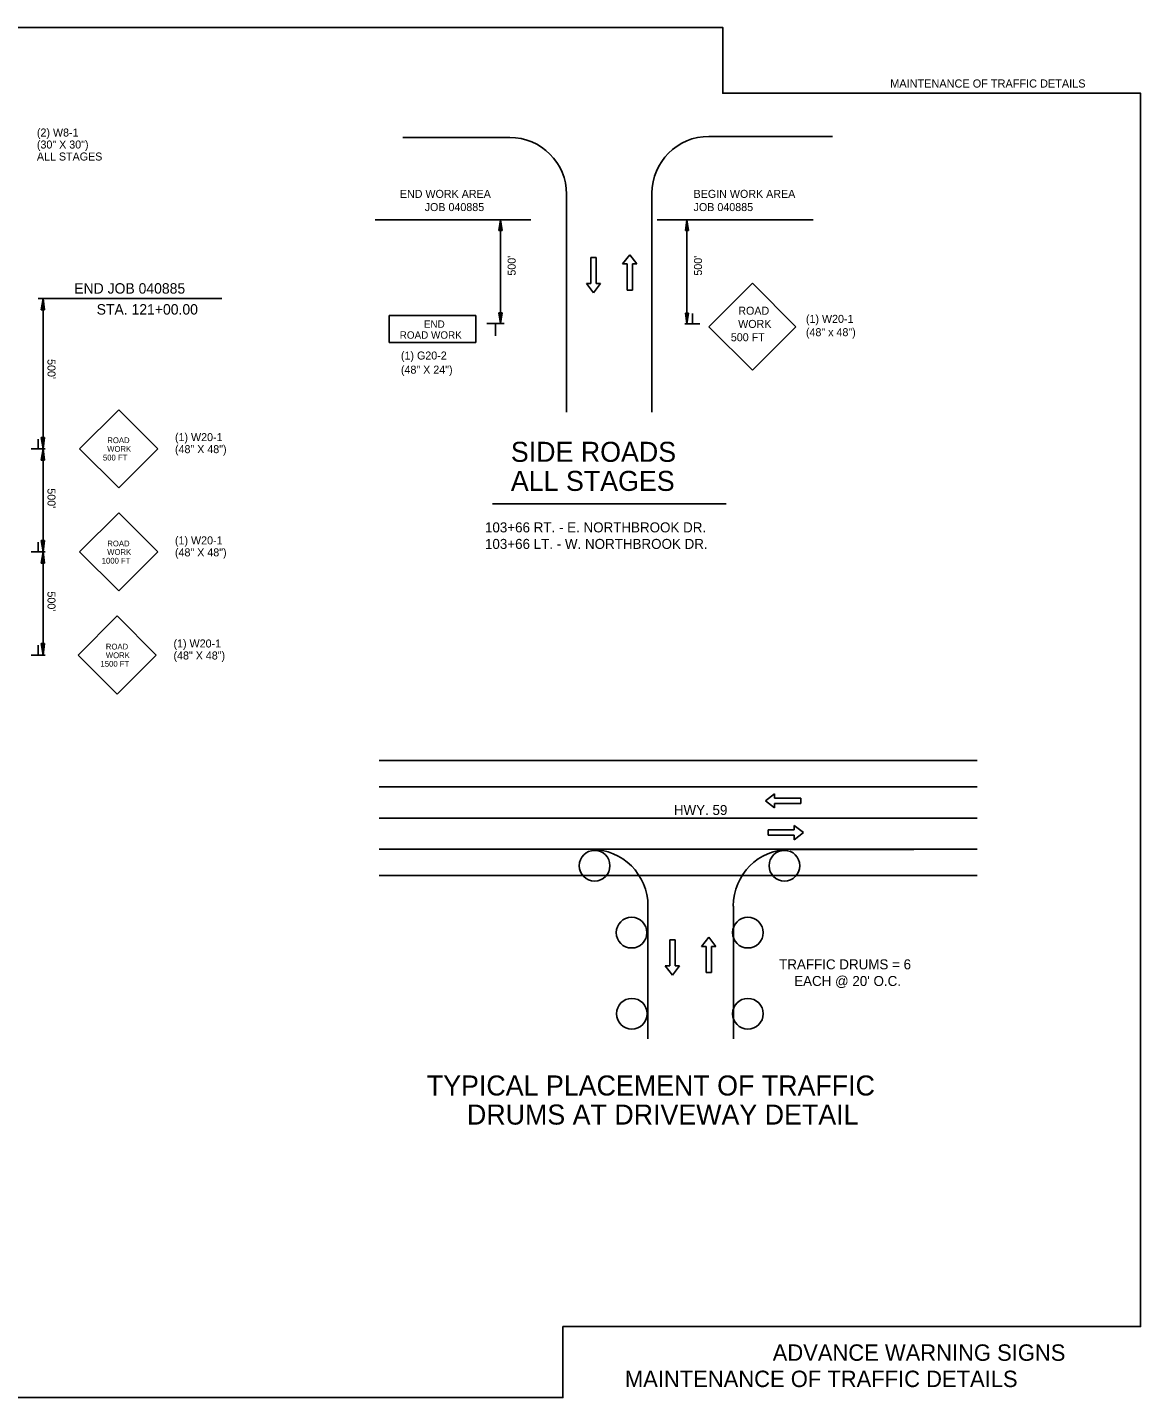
# Model space of a CAD drawing. Extents: x 612778 to 616168, y 428753 to 429781.
# Drawn here: x 613525 to 614359, y 428753 to 429781 of the extents above; entities that cross this region are included whole.
import ezdxf

# ---------------------------------------------------------------- set-up
doc = ezdxf.new("R2010")
doc.units = 0
for name, color, linetype in [('Level 8', 7, 'Continuous'), ('Plan Notes', 7, 'Continuous'), ('R_Draft', 7, 'Continuous'), ('R_No Plot', 7, 'Continuous'), ('STAGE 1 BARRELS', 7, 'Continuous')]:
    doc.layers.add(name, color=color, linetype=linetype)

msp = doc.modelspace()

# ---------------------------------------------------------------- linework, layer by layer
at = {"layer": 'Level 8'}
for p, q in [((613593.3, 429493.9), (613564, 429464.6)), ((613622.6, 429464.6), (613593.3, 429493.9)), ((613593.3, 429435.3), (613564, 429464.6)), ((613622.6, 429464.6), (613593.3, 429435.3)), ((613593.3, 429416.6), (613564, 429387.3)), ((613622.6, 429387.3), (613593.3, 429416.6)), ((613593.3, 429358), (613564, 429387.3)), ((613622.6, 429387.3), (613593.3, 429358)), ((613592.2, 429339.3), (613562.9, 429309.9)), ((613621.5, 429309.9), (613592.2, 429339.3)), ((613592.2, 429280.6), (613562.9, 429309.9)), ((613621.5, 429309.9), (613592.2, 429280.6))]:
    msp.add_line(p, q, dxfattribs=at)
at = {"layer": 'Plan Notes'}
for p, q in [((613886.5, 429697.9), (613806.4, 429697.9)), ((614128.4, 429698.8), (614035.7, 429698.8)), ((613929.1, 429492), (613929.1, 429655.4)), ((613993.1, 429492), (613993.1, 429656.2)), ((613785.5, 429636.3), (613902.3, 429636.3)), ((613878.4, 429628.3), (613879.6, 429636.3)), ((613878.4, 429628.3), (613880.8, 429628.3)), ((613878.6, 429628.3), (613879.6, 429634.9)), ((613878.8, 429628.3), (613879.6, 429633.6)), ((613879, 429628.3), (613879.6, 429632.2)), ((613879.2, 429628.3), (613879.6, 429630.9)), ((613879.4, 429628.3), (613879.6, 429629.6)), ((613880.8, 429628.3), (613879.6, 429636.3)), ((613879.6, 429636.3), (613879.6, 429558.5)), ((613880.6, 429628.3), (613879.6, 429634.9)), ((613880.4, 429628.3), (613879.6, 429633.6)), ((613880.2, 429628.3), (613879.6, 429632.2)), ((613880, 429628.3), (613879.6, 429630.9)), ((613879.8, 429628.3), (613879.6, 429629.6)), ((614113.9, 429636.3), (613997.1, 429636.3)), ((614018.1, 429628.3), (614019.3, 429636.3)), ((614018.1, 429628.3), (614020.5, 429628.3)), ((614018.3, 429628.3), (614019.3, 429634.9)), ((614018.5, 429628.3), (614019.3, 429633.6)), ((614018.7, 429628.3), (614019.3, 429632.2)), ((614018.9, 429628.3), (614019.3, 429630.9)), ((614019.1, 429628.3), (614019.3, 429629.6)), ((614020.5, 429628.3), (614019.3, 429636.3)), ((614019.3, 429636.3), (614019.3, 429558.3)), ((614020.3, 429628.3), (614019.3, 429634.9)), ((614020.1, 429628.3), (614019.3, 429633.6)), ((614019.9, 429628.3), (614019.3, 429632.2)), ((614019.7, 429628.3), (614019.3, 429630.9)), ((614019.5, 429628.3), (614019.3, 429629.6)), ((613947.2, 429588.5), (613947.2, 429608.1)), ((613951.2, 429608.1), (613947.2, 429608.1)), ((613951.2, 429588.5), (613951.2, 429608.1)), ((613971.1, 429603.2), (613976.4, 429610.1)), ((613976.4, 429610.1), (613981.7, 429603.2)), ((613971.1, 429603.2), (613974.4, 429603.2)), ((613974.4, 429603.2), (613974.4, 429583.6)), ((613978.4, 429603.2), (613978.4, 429583.6)), ((613978.4, 429603.2), (613981.7, 429603.2)), ((613947.2, 429588.5), (613943.9, 429588.5)), ((613949.2, 429581.6), (613943.9, 429588.5)), ((613954.5, 429588.5), (613949.2, 429581.6)), ((613954.5, 429588.5), (613951.2, 429588.5)), ((614068.4, 429588.8), (614035.7, 429556.1)), ((614101, 429556.1), (614068.4, 429588.8)), ((613533, 429577.3), (613670.7, 429577.3)), ((613535.3, 429568.8), (613536.6, 429577.3)), ((613535.5, 429568.8), (613536.6, 429575.9)), ((613536.6, 429532.2), (613536.6, 429577.3)), ((613537.8, 429568.8), (613536.6, 429577.3)), ((613537.6, 429568.8), (613536.6, 429575.9)), ((613974.4, 429583.6), (613978.4, 429583.6)), ((613535.3, 429568.8), (613537.8, 429568.8)), ((613535.7, 429568.8), (613536.6, 429574.4)), ((613535.9, 429568.8), (613536.6, 429573)), ((613536.1, 429568.8), (613536.6, 429571.5)), ((613536.4, 429568.8), (613536.6, 429570.1)), ((613537.4, 429568.8), (613536.6, 429574.4)), ((613537.2, 429568.8), (613536.6, 429573)), ((613537, 429568.8), (613536.6, 429571.5)), ((613536.8, 429568.8), (613536.6, 429570.1)), ((613878.4, 429566.5), (613879.6, 429558.5)), ((613880.8, 429566.5), (613878.4, 429566.5)), ((613878.6, 429566.5), (613879.6, 429559.8)), ((613878.8, 429566.5), (613879.6, 429561.2)), ((613879, 429566.5), (613879.6, 429562.5)), ((613879.2, 429566.5), (613879.6, 429563.9)), ((613879.4, 429566.5), (613879.6, 429565.2)), ((613880.8, 429566.5), (613879.6, 429558.5)), ((613880, 429566.5), (613879.6, 429563.9)), ((613880.4, 429566.5), (613879.6, 429561.2)), ((613880.6, 429566.5), (613879.6, 429559.8)), ((613880.2, 429566.5), (613879.6, 429562.5)), ((613879.8, 429566.5), (613879.6, 429565.2)), ((614018.1, 429566.3), (614019.3, 429558.3)), ((614020.5, 429566.3), (614018.1, 429566.3)), ((614018.3, 429566.3), (614019.3, 429559.6)), ((614018.5, 429566.3), (614019.3, 429561)), ((614018.7, 429566.3), (614019.3, 429562.3)), ((614018.9, 429566.3), (614019.3, 429563.7)), ((614019.1, 429566.3), (614019.3, 429565)), ((614020.5, 429566.3), (614019.3, 429558.3)), ((614019.7, 429566.3), (614019.3, 429563.7)), ((614020.1, 429566.3), (614019.3, 429561)), ((614020.3, 429566.3), (614019.3, 429559.6)), ((614019.9, 429566.3), (614019.3, 429562.3)), ((614019.5, 429566.3), (614019.3, 429565)), ((614023.4, 429558.4), (614023.4, 429566.1)), ((613861.1, 429564.6), (613796.2, 429564.6)), ((613796.2, 429544.2), (613796.2, 429564.6)), ((613861.1, 429544.2), (613861.1, 429564.6)), ((613882.4, 429558.5), (613869.2, 429558.5)), ((613875.8, 429558.3), (613875.8, 429549.3)), ((614029, 429558.2), (614017.7, 429558.3)), ((614068.4, 429523.5), (614035.7, 429556.1)), ((614101, 429556.1), (614068.4, 429523.5)), ((613861.1, 429544.2), (613796.2, 429544.2)), ((613536.6, 429464.6), (613536.6, 429532.2)), ((613535.3, 429473.1), (613536.6, 429464.6)), ((613537.8, 429473.1), (613535.3, 429473.1)), ((613535.5, 429473.1), (613536.6, 429466)), ((613535.7, 429473.1), (613536.6, 429467.5)), ((613535.9, 429473.1), (613536.6, 429468.9)), ((613536.1, 429473.1), (613536.6, 429470.3)), ((613536.4, 429473.1), (613536.6, 429471.8)), ((613537.8, 429473.1), (613536.6, 429464.6)), ((613537, 429473.1), (613536.6, 429470.3)), ((613537.4, 429473.1), (613536.6, 429467.5)), ((613537.6, 429473.1), (613536.6, 429466)), ((613537.2, 429473.1), (613536.6, 429468.9)), ((613536.8, 429473.1), (613536.6, 429471.8)), ((613538.2, 429464.6), (613527.7, 429464.6)), ((613533, 429464.7), (613533, 429471.9)), ((613535.3, 429456.1), (613536.6, 429464.6)), ((613535.5, 429456.1), (613536.6, 429463.2)), ((613536.6, 429387.3), (613536.6, 429464.6)), ((613537.8, 429456.1), (613536.6, 429464.6)), ((613537.6, 429456.1), (613536.6, 429463.2)), ((613535.3, 429456.1), (613537.8, 429456.1)), ((613535.7, 429456.1), (613536.6, 429461.7)), ((613535.9, 429456.1), (613536.6, 429460.3)), ((613536.1, 429456.1), (613536.6, 429458.8)), ((613536.4, 429456.1), (613536.6, 429457.4)), ((613537.4, 429456.1), (613536.6, 429461.7)), ((613537.2, 429456.1), (613536.6, 429460.3)), ((613537, 429456.1), (613536.6, 429458.8)), ((613536.8, 429456.1), (613536.6, 429457.4)), ((613873.5, 429423.2), (614048.7, 429423.2)), ((613533, 429387.4), (613533, 429394.6)), ((613535.3, 429395.8), (613536.6, 429387.3)), ((613537.8, 429395.8), (613535.3, 429395.8)), ((613535.5, 429395.8), (613536.6, 429388.7)), ((613535.7, 429395.8), (613536.6, 429390.1)), ((613535.9, 429395.8), (613536.6, 429391.6)), ((613536.1, 429395.8), (613536.6, 429393)), ((613536.4, 429395.8), (613536.6, 429394.4)), ((613537.8, 429395.8), (613536.6, 429387.3)), ((613537, 429395.8), (613536.6, 429393)), ((613537.4, 429395.8), (613536.6, 429390.1)), ((613537.6, 429395.8), (613536.6, 429388.7)), ((613537.2, 429395.8), (613536.6, 429391.6)), ((613536.8, 429395.8), (613536.6, 429394.4)), ((613538.2, 429387.3), (613527.7, 429387.3)), ((613535.3, 429378.7), (613536.6, 429387.3)), ((613535.5, 429378.7), (613536.6, 429385.8)), ((613535.7, 429378.7), (613536.6, 429384.4)), ((613535.9, 429378.7), (613536.6, 429382.9)), ((613536.1, 429378.7), (613536.6, 429381.5)), ((613537.8, 429378.7), (613536.6, 429387.3)), ((613536.6, 429309.9), (613536.6, 429387.3)), ((613537.6, 429378.7), (613536.6, 429385.8)), ((613537.4, 429378.7), (613536.6, 429384.4)), ((613537.2, 429378.7), (613536.6, 429382.9)), ((613537, 429378.7), (613536.6, 429381.5)), ((613535.3, 429378.7), (613537.8, 429378.7)), ((613536.4, 429378.7), (613536.6, 429380.1)), ((613536.8, 429378.7), (613536.6, 429380.1)), ((613538.2, 429309.9), (613527.7, 429309.9)), ((613533, 429310.1), (613533, 429317.3)), ((613535.3, 429318.5), (613536.6, 429309.9)), ((613537.8, 429318.5), (613535.3, 429318.5)), ((613535.5, 429318.5), (613536.6, 429311.4)), ((613535.7, 429318.5), (613536.6, 429312.8)), ((613535.9, 429318.5), (613536.6, 429314.2)), ((613536.1, 429318.5), (613536.6, 429315.7)), ((613536.4, 429318.5), (613536.6, 429317.1)), ((613537.8, 429318.5), (613536.6, 429309.9)), ((613537, 429318.5), (613536.6, 429315.7)), ((613537.4, 429318.5), (613536.6, 429312.8)), ((613537.6, 429318.5), (613536.6, 429311.4)), ((613537.2, 429318.5), (613536.6, 429314.2)), ((613536.8, 429318.5), (613536.6, 429317.1)), ((614236.9, 429230.8), (613788.7, 429230.8)), ((614236.9, 429211.2), (613788.7, 429211.2)), ((614078.1, 429200.6), (614085, 429206)), ((614085, 429202.6), (614085, 429206)), ((614085, 429195.3), (614078.1, 429200.6)), ((614085, 429202.6), (614104.6, 429202.6)), ((614085, 429198.6), (614104.6, 429198.6)), ((614085, 429195.3), (614085, 429198.6)), ((614104.6, 429198.6), (614104.6, 429202.6)), ((614236.9, 429187.7), (613788.7, 429187.7)), ((614099.7, 429178.9), (614080.1, 429178.9)), ((614080.1, 429178.9), (614080.1, 429174.9)), ((614099.7, 429182.2), (614099.7, 429178.9)), ((614099.7, 429182.2), (614106.6, 429176.9)), ((614106.6, 429176.9), (614099.7, 429171.5)), ((614099.7, 429174.9), (614080.1, 429174.9)), ((614099.7, 429174.9), (614099.7, 429171.5)), ((614236.9, 429164.3), (613788.7, 429164.3)), ((613947.5, 429164.3), (613867.4, 429164.3)), ((614189.3, 429164.2), (614096.6, 429164.2)), ((614236.9, 429144.7), (613788.7, 429144.7)), ((613990.1, 429022.3), (613990.1, 429121.7)), ((614054.1, 429022.3), (614054.1, 429121.7)), ((614006.5, 429076.8), (614006.5, 429096.4)), ((614010.5, 429096.4), (614006.5, 429096.4)), ((614010.5, 429076.8), (614010.5, 429096.4)), ((614030.3, 429091.4), (614035.6, 429098.4)), ((614035.6, 429098.4), (614041, 429091.4)), ((614030.3, 429091.4), (614033.6, 429091.4)), ((614033.6, 429091.4), (614033.6, 429071.8)), ((614037.6, 429091.4), (614037.6, 429071.8)), ((614037.6, 429091.4), (614041, 429091.4)), ((614006.5, 429076.8), (614003.1, 429076.8)), ((614008.5, 429069.9), (614003.1, 429076.8)), ((614013.8, 429076.8), (614008.5, 429069.9)), ((614013.8, 429076.8), (614010.5, 429076.8)), ((614033.6, 429071.8), (614037.6, 429071.8))]:
    msp.add_line(p, q, dxfattribs=at)
for centre, start, end in [((613886.5, 429655.4), 360, 90), ((614035.7, 429656.2), 90, 180), ((613947.5, 429121.7), 360, 90), ((614096.6, 429121.7), 90, 180)]:
    msp.add_arc(centre, 42.6, start, end, dxfattribs=at)
at = {"layer": 'R_No Plot'}
msp.add_lwpolyline([(614359.4, 429266.9), (614359.4, 429731.1), (614046.2, 429731.1), (614046.2, 429780.5), (612778.5, 429780.5), (612778.5, 428753.2), (613926.3, 428753.2), (613926.3, 428806.4), (614359.4, 428806.4)], close=True, dxfattribs=at)
at = {"layer": 'STAGE 1 BARRELS'}
for centre in [(613950.1, 429152), (614092.4, 429152), (613977.8, 429101.8), (614065, 429101.8), (613978, 429041), (614065, 429041)]:
    msp.add_circle(centre, 11.5, dxfattribs=at)

# ---------------------------------------------------------------- texts
at = {"layer": 'Level 8'}
for s, p in [('(2) W8-1', (613532, 429698.7)), ('(30" X 30")', (613532, 429689.7)), ('ALL STAGES', (613532, 429680.7))]:
    msp.add_text(s, height=6, dxfattribs=at).set_placement(p)
for s, height, rotation, p in [('ROAD', 4.32, 359.9993, (613584.8, 429468.8)), ('(1) W20-1', 6, 359.9988, (613635.5, 429470.3)), ('WORK', 4.32, 359.9989, (613584.7, 429462.3)), ('(48" X 48")', 6, 359.9988, (613635.5, 429461.3)), ('500 FT', 4.32, 359.9994, (613581.5, 429455.8)), ('ROAD', 4.32, 359.9993, (613584.8, 429391.4)), ('(1) W20-1', 6, 359.9988, (613635.5, 429392.9)), ('1000 FT', 4.32, 359.9994, (613580.6, 429378.5)), ('WORK', 4.32, 359.9989, (613584.7, 429385)), ('(48" X 48")', 6, 359.9988, (613635.5, 429383.9)), ('(1) W20-1', 6, 359.9988, (613634.4, 429315.6)), ('WORK', 4.32, 359.9989, (613583.7, 429307.6)), ('ROAD', 4.32, 359.9993, (613583.7, 429314.1)), ('(48" X 48")', 6, 359.9988, (613634.4, 429306.6)), ('1500 FT', 4.32, 359.9994, (613579.7, 429301.2))]:
    msp.add_text(s, height=height, rotation=rotation, dxfattribs=at).set_placement(p)
at = {"layer": 'Plan Notes'}
for s, height, rotation, p in [('END WORK AREA', 6, 360, (613804.1, 429652.7)), ('BEGIN WORK AREA', 6, 360, (614024.3, 429652.7)), ('JOB 040885', 6, 360, (613822.7, 429642.8)), ('JOB 040885', 6, 360, (614024.3, 429642.8)), ("500'", 6, 90, (613890.9, 429594.4)), ("500'", 6, 90, (614030.6, 429594.4)), ('END JOB 040885', 7.823, 360, (613560, 429580.9)), ('STA. 121+00.00', 7.823, 360, (613576.8, 429565.2)), ('ROAD', 6, 0, (614057.8, 429565.1)), ('END', 5.54, 360, (613822.1, 429555.3)), ('WORK', 6, 0, (614057.7, 429555.2)), ('ROAD WORK', 5.54, 360, (613804, 429547.1)), ('500 FT', 6, 0, (614052.2, 429545.2)), ('(1) G20-2', 6, 360, (613804.9, 429531.5)), ("500'", 6, 270.3189, (613539.9, 429531.8)), ('(48" X 24")', 6, 360, (613804.9, 429520.9)), ('SIDE ROADS', 15.02, 360, (613887.3, 429454.8)), ('ALL STAGES', 15.02, 360, (613887.3, 429433)), ("500'", 6, 270.3189, (613539.9, 429434.9)), ('103+66 RT. - E. NORTHBROOK DR.', 7.5, 0, (613867.9, 429401.9)), ('103+66 LT. - W. NORTHBROOK DR.', 7.5, 0, (613867.9, 429389.5)), ("500'", 6, 270.3189, (613539.9, 429357.6)), ('HWY. 59', 7.5, 0, (614009.5, 429190)), ('TRAFFIC DRUMS = 6 ', 7.5, 0, (614088.4, 429074.3)), ("EACH @ 20' O.C.", 7.5, 0, (614099.7, 429061.8)), ('TYPICAL PLACEMENT OF TRAFFIC', 15.021, 360, (613824.3, 428979.7)), ('DRUMS AT DRIVEWAY DETAIL', 15.021, 360, (613854.4, 428957.9))]:
    msp.add_text(s, height=height, rotation=rotation, dxfattribs=at).set_placement(p)
for s, p in [('(1) W20-1', (614108.5, 429559)), ('(48" x 48")', (614108.5, 429549))]:
    msp.add_text(s, height=6, dxfattribs=at).set_placement(p)
at = {"layer": 'R_Draft'}
for s, height, p in [('MAINTENANCE OF TRAFFIC DETAILS', 6.12, (614171.7, 429735.4)), ('ADVANCE WARNING SIGNS ', 12.305, (614083.6, 428780.8)), ('MAINTENANCE OF TRAFFIC DETAILS', 12.305, (613972.8, 428761.1))]:
    msp.add_text(s, height=height, dxfattribs=at).set_placement(p)

doc.saveas('drawing.dxf')
